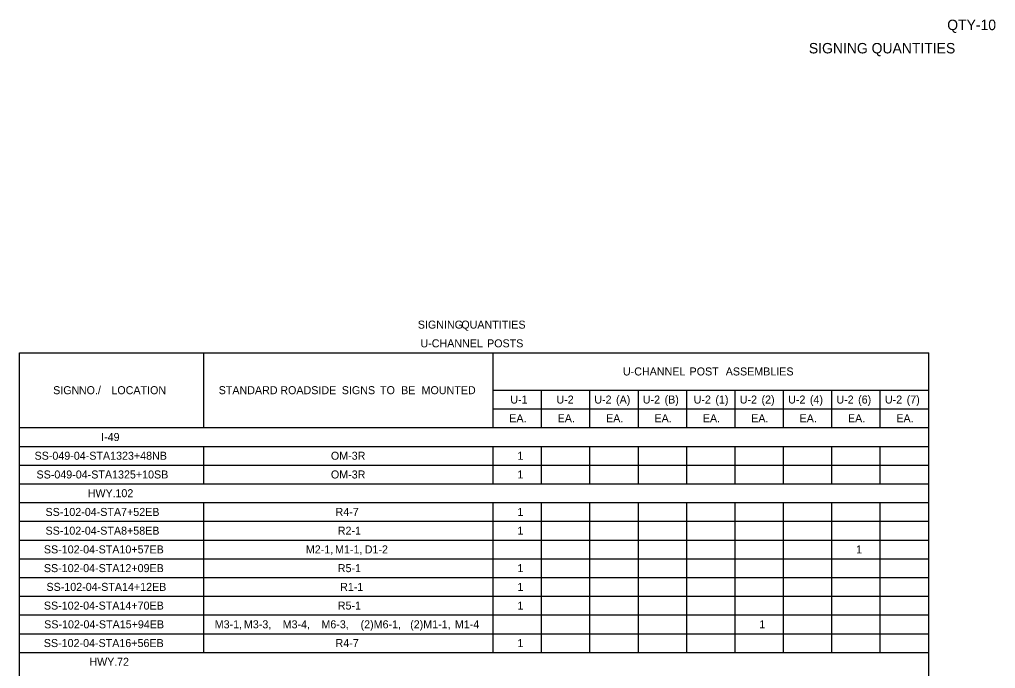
# Model space of a CAD drawing. Extents: x 1226613 to 1228135, y 151309 to 152326.
# Drawn here: x 1227562 to 1228111, y 151941 to 152305 of the extents above; entities that cross this region are included whole.
import ezdxf

# ---------------------------------------------------------------- set-up
doc = ezdxf.new("R2010")
doc.units = 0
doc.layers.add('R_Border', color=7, linetype='Continuous')
doc.layers.add('R_Dimension', color=7, linetype='Continuous')

msp = doc.modelspace()

# ---------------------------------------------------------------- linework, layer by layer
at = {"layer": 'R_Dimension'}
for p, q in [((1227562.3, 152118.19), (1228073.44, 152118.19)), ((1227562.3, 151549.57), (1227562.3, 152118.19)), ((1227665.84, 152076.07), (1227665.84, 152118.19)), ((1227828.62, 152076.07), (1227828.62, 152118.19)), ((1228073.44, 151549.57), (1228073.44, 152118.19)), ((1227828.62, 152097.13), (1228073.44, 152097.13)), ((1227855.82, 152076.07), (1227855.82, 152097.13)), ((1227883.02, 152076.07), (1227883.02, 152097.13)), ((1227910.23, 152076.07), (1227910.23, 152097.13)), ((1227937.43, 152076.07), (1227937.43, 152097.13)), ((1227964.63, 152076.07), (1227964.63, 152097.13)), ((1227991.83, 152076.07), (1227991.83, 152097.13)), ((1228019.04, 152076.07), (1228019.04, 152097.13)), ((1228046.24, 152076.07), (1228046.24, 152097.13)), ((1227828.62, 152086.6), (1228073.44, 152086.6)), ((1227562.3, 152076.07), (1228073.44, 152076.07)), ((1227562.3, 152065.54), (1228073.44, 152065.54)), ((1227665.84, 152044.48), (1227665.84, 152065.54)), ((1227828.62, 152044.48), (1227828.62, 152065.54)), ((1227855.82, 152044.48), (1227855.82, 152065.54)), ((1227883.02, 152044.48), (1227883.02, 152065.54)), ((1227910.23, 152044.48), (1227910.23, 152065.54)), ((1227937.43, 152044.48), (1227937.43, 152065.54)), ((1227964.63, 152044.48), (1227964.63, 152065.54)), ((1227991.83, 152044.48), (1227991.83, 152065.54)), ((1228019.04, 152044.48), (1228019.04, 152065.54)), ((1228046.24, 152044.48), (1228046.24, 152065.54)), ((1227562.3, 152055.01), (1228073.44, 152055.01)), ((1227562.3, 152044.48), (1228073.44, 152044.48)), ((1227562.3, 152033.95), (1228073.44, 152033.95)), ((1227665.84, 151949.71), (1227665.84, 152033.95)), ((1227828.62, 151949.71), (1227828.62, 152033.95)), ((1227855.82, 151949.71), (1227855.82, 152033.95)), ((1227883.02, 151949.71), (1227883.02, 152033.95)), ((1227910.23, 151949.71), (1227910.23, 152033.95)), ((1227937.43, 151949.71), (1227937.43, 152033.95)), ((1227964.63, 151949.71), (1227964.63, 152033.95)), ((1227991.83, 151949.71), (1227991.83, 152033.95)), ((1228019.04, 151949.71), (1228019.04, 152033.95)), ((1228046.24, 151949.71), (1228046.24, 152033.95)), ((1227562.3, 152023.42), (1228073.44, 152023.42)), ((1227562.3, 152012.89), (1228073.44, 152012.89)), ((1227562.3, 152002.36), (1228073.44, 152002.36)), ((1227562.3, 151991.83), (1228073.44, 151991.83)), ((1227562.3, 151981.3), (1228073.44, 151981.3)), ((1227562.3, 151970.77), (1228073.44, 151970.77)), ((1227562.3, 151960.24), (1228073.44, 151960.24)), ((1227562.3, 151949.71), (1228073.44, 151949.71))]:
    msp.add_line(p, q, dxfattribs=at)

# ---------------------------------------------------------------- texts
at = {"layer": 'R_Border'}
for s, height, p in [('QTY-10', 5.861, (1228083.86, 152299.55)), ('SIGNING QUANTITIES', 5.862, (1228006.08, 152286.45))]:
    msp.add_text(s, height=height, dxfattribs=at).set_placement(p)
at = {"layer": 'R_Dimension'}
for s, p in [('SIGNING', (1227786.23, 152131.74)), (' QUANTITIES', (1227809.01, 152131.74)), ('U-CHANNEL', (1227787.7, 152121.21)), (' POSTS', (1227823.49, 152121.21)), ('U-CHANNEL', (1227901.55, 152105.41)), (' POST', (1227937.34, 152105.41)), (' ASSEMBLIES', (1227957.67, 152105.41)), ('SIGN', (1227581.21, 152094.88)), (' NO./', (1227594, 152094.88)), (' LOCATION', (1227612.28, 152094.88)), ('STANDARD', (1227674.27, 152094.88)), (' ROADSIDE', (1227707.26, 152094.88)), (' SIGNS', (1227741.81, 152094.88)), (' TO', (1227763.32, 152094.88)), (' BE', (1227775.15, 152094.88)), (' MOUNTED', (1227786.67, 152094.88)), ('U-1', (1227838.22, 152089.62)), ('U-2', (1227864.14, 152089.62)), ('U-2', (1227885.45, 152089.62)), (' (A)', (1227896.01, 152089.62)), ('U-2', (1227912.72, 152089.62)), (' (B)', (1227923.28, 152089.62)), ('U-2', (1227941.3, 152089.62)), (' (1)', (1227951.86, 152089.62)), ('U-2', (1227967.23, 152089.62)), (' (2)', (1227977.79, 152089.62)), ('U-2', (1227994.43, 152089.62)), (' (4)', (1228004.99, 152089.62)), ('U-2', (1228021.53, 152089.62)), (' (6)', (1228032.09, 152089.62)), ('U-2', (1228048.84, 152089.62)), (' (7)', (1228059.4, 152089.62)), ('EA.', (1227837.65, 152079.09)), ('EA.', (1227864.85, 152079.09)), ('EA.', (1227892.05, 152079.09)), ('EA.', (1227919.26, 152079.09)), ('EA.', (1227946.46, 152079.09)), ('EA.', (1227973.66, 152079.09)), ('EA.', (1228000.86, 152079.09)), ('EA.', (1228028.07, 152079.09)), ('EA.', (1228055.27, 152079.09)), ('I-49', (1227608.17, 152068.56)), ('SS-049-04-STA1323+48NB', (1227570.75, 152058.03)), ('OM-3R', (1227737.36, 152058.03)), ('1', (1227842.22, 152058.03)), ('SS-049-04-STA1325+10SB', (1227571.85, 152047.5)), ('OM-3R', (1227737.36, 152047.5)), ('1', (1227842.22, 152047.5)), ('HWY.', (1227600.66, 152036.97)), (' 102', (1227614.55, 152036.97)), ('SS-102-04-STA7+52EB', (1227576.92, 152026.44)), ('R4-7', (1227739.97, 152026.44)), ('1', (1227842.22, 152026.44)), ('SS-102-04-STA8+58EB', (1227576.92, 152015.91)), ('R2-1', (1227741.24, 152015.91)), ('1', (1227842.22, 152015.91)), ('SS-102-04-STA10+57EB', (1227576, 152005.38)), ('M2-1,', (1227723.28, 152005.38)), (' M1-1,', (1227738.02, 152005.38)), (' D1-2', (1227754.71, 152005.38)), ('1', (1228032.64, 152005.38)), ('SS-102-04-STA12+09EB', (1227576, 151994.85)), ('R5-1', (1227741.24, 151994.85)), ('1', (1227842.22, 151994.85)), ('SS-102-04-STA14+12EB', (1227577.45, 151984.32)), ('R1-1', (1227742.52, 151984.32)), ('1', (1227842.22, 151984.32)), ('SS-102-04-STA14+70EB', (1227576, 151973.79)), ('R5-1', (1227741.24, 151973.79)), ('1', (1227842.22, 151973.79)), ('SS-102-04-STA15+94EB', (1227576.17, 151963.26)), ('M3-1,', (1227672.04, 151963.26)), (' M3-3,', (1227686.78, 151963.26)), (' M3-4,', (1227708.57, 151963.26)), (' M6-3,', (1227730.36, 151963.26)), (' (2)M6-1,', (1227752.37, 151963.26)), (' (2)M1-1,', (1227780.25, 151963.26)), (' M1-4', (1227805.38, 151963.26)), ('1', (1227978.23, 151963.26)), ('SS-102-04-STA16+56EB', (1227575.96, 151952.73)), ('R4-7', (1227739.97, 151952.73)), ('1', (1227842.22, 151952.73)), ('HWY.', (1227601.58, 151942.2)), (' 72', (1227615.47, 151942.2))]:
    msp.add_text(s, height=4.5, dxfattribs=at).set_placement(p)

doc.saveas('drawing.dxf')
